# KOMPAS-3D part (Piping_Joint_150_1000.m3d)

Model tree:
1. Plane XY
2. Plane ZX
3. Plane ZY
4. X Axis
5. Y Axis
6. Z Axis
7. Origin
8. Sketch:1
9. Extrude:1  (labels: На расстояние 1; На расстояние 2)
     Толщина стенки 1 = 1; Толщина стенки 2 = 1; Расстояние 1 = 2; Расстояние 2 = 10
10. Sketch:2
11. Attachment Point:1
12. Attachment Point:2  (labels: C:\Program Files\ASCON\KOMPAS-3D V10\Sys\graphic.lyt; Joint Dn 150; Piping_Joint_150_1000.m3d; Tanks_step 1.a3d)

Referenced files in C:\Documents and Settings\kashirsky\Мои документы\Camtasia Studio\Pipelines3D\Tanks\: Piping_Joint_150_1000.m3d, Tanks_step 1.a3d, Tanks_step 1.spw, Tanks_step 2.a3d, Tanks_step 3.a3d, Tanks_step 4.a3d
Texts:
  Joint Dn 150
  Three Point Plane
  Plane at Angle
  Line and Point Plane
  Axis through Two Vertices
  Axis of Feature
  Axis of Conical Surface
  Axis through Edge
  Приклеить элемент выдавливания
  Приклеить элемент вращения
  Приклеить кинематический элемент
  Приклеить элемент по сечениям
  Trim by Surface
  Trim by Sketch
  Feature with No History
  Intersection Axis of Two Planes
  Two Line Plane
  Line and Face Plane
  Bend by line
  Hole in sheet body
  Cut in sheet body
  Point in CM
  Linear Dimension from Line to Point
  Surface Finish Symbol
  Geometric Tolerance Symbol
  Текст на чертеже
  Линия-выноска #1
  Линия-выноска #2
  Линия-выноска #3
  Отклонения формы и база
  Марка координационной оси
  Марка/позиционное обозначение с линией-выноской
  Марка/позиционное обозначение на линии
  Марка/позиционное обозначение без линии-выноски
  На расстояние 1
  На расстояние 2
